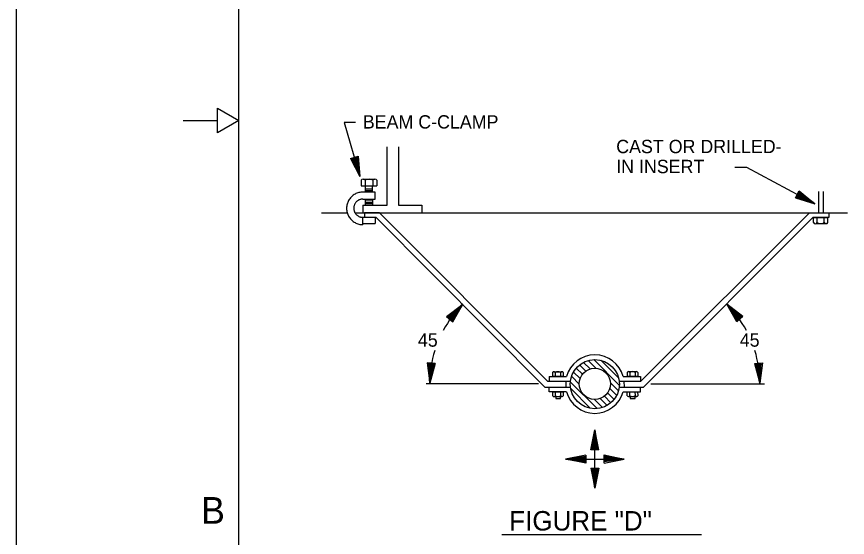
# Model space of a CAD drawing. Extents: x 10040.55 to 10045.84, y 10033.26 to 10035.76.
# Drawn here: x 10040.547 to 10041.17, y 10034.193 to 10034.583 of the extents above; entities that cross this region are included whole.
import ezdxf

# ---------------------------------------------------------------- set-up
doc = ezdxf.new("R2010")
doc.units = 0
doc.layers.add('Level 1', color=7, linetype='Continuous')
doc.layers.add('Level 2', color=7, linetype='Continuous')

msp = doc.modelspace()

# ---------------------------------------------------------------- linework, layer by layer
at = {"layer": 'Level 1'}
for p, q in [((10040.54697, 10033.25552), (10040.54697, 10035.75552)), ((10040.71364, 10033.29719), (10040.71364, 10035.71385)), ((10040.69764, 10034.49619), (10040.69764, 10034.5146)), ((10040.69764, 10034.5146), (10040.71364, 10034.50552)), ((10040.67197, 10034.50552), (10040.69764, 10034.50552)), ((10040.71364, 10034.50552), (10040.69764, 10034.49619))]:
    msp.add_line(p, q, dxfattribs=at)
at = {"layer": 'Level 2'}
for p, q in [((10040.82507, 10034.44193), (10040.82507, 10034.48575)), ((10040.83347, 10034.48575), (10040.83347, 10034.44193)), ((10040.79736, 10034.47697), (10040.80316, 10034.47861)), ((10040.80436, 10034.46331), (10040.80096, 10034.47799)), ((10040.80436, 10034.46331), (10040.80167, 10034.47821)), ((10040.80436, 10034.46331), (10040.80236, 10034.4784)), ((10040.80316, 10034.47861), (10040.80436, 10034.46331)), ((10040.79736, 10034.47697), (10040.80436, 10034.46331)), ((10040.80436, 10034.46331), (10040.79809, 10034.47719)), ((10040.80436, 10034.46331), (10040.79891, 10034.47744)), ((10040.80436, 10034.46331), (10040.79955, 10034.47759)), ((10040.80023, 10034.4778), (10040.80436, 10034.46331)), ((10040.8055, 10034.46057), (10040.80547, 10034.45646)), ((10040.80695, 10034.46146), (10040.81578, 10034.46146)), ((10040.8084, 10034.46056), (10040.8084, 10034.45646)), ((10040.81433, 10034.46057), (10040.81433, 10034.45643)), ((10040.81726, 10034.46057), (10040.81727, 10034.45646)), ((10040.80547, 10034.45646), (10040.81727, 10034.45646)), ((10040.81392, 10034.45399), (10040.80873, 10034.45399)), ((10040.80875, 10034.45172), (10040.80875, 10034.45642)), ((10040.81389, 10034.45172), (10040.81389, 10034.45642)), ((10040.81593, 10034.45172), (10040.80677, 10034.45172)), ((10040.80873, 10034.45294), (10040.81392, 10034.45294)), ((10040.81593, 10034.44646), (10040.81593, 10034.45172)), ((10041.13127, 10034.44748), (10041.13411, 10034.45279)), ((10041.13127, 10034.44748), (10041.14596, 10034.44303)), ((10041.14596, 10034.44303), (10041.13163, 10034.44816)), ((10041.14596, 10034.44303), (10041.13201, 10034.44892)), ((10041.14596, 10034.44303), (10041.13234, 10034.44949)), ((10041.13267, 10034.45011), (10041.14596, 10034.44303)), ((10041.14596, 10034.44303), (10041.13303, 10034.45078)), ((10041.14596, 10034.44303), (10041.13338, 10034.45144)), ((10041.14596, 10034.44303), (10041.13372, 10034.45207)), ((10041.13411, 10034.45279), (10041.14596, 10034.44303)), ((10041.1486, 10034.45223), (10041.1486, 10034.43634)), ((10041.15201, 10034.45223), (10041.15201, 10034.43634)), ((10040.80677, 10034.44646), (10040.81593, 10034.44646)), ((10040.80677, 10034.44193), (10040.82507, 10034.44193)), ((10040.80677, 10034.44193), (10040.80677, 10034.43622)), ((10040.81392, 10034.44557), (10040.80873, 10034.44557)), ((10040.81385, 10034.44303), (10040.80873, 10034.44303)), ((10040.80875, 10034.44189), (10040.80875, 10034.4465)), ((10040.80879, 10034.44416), (10040.81392, 10034.44416)), ((10040.81389, 10034.4465), (10040.81389, 10034.44189)), ((10040.83347, 10034.44193), (10040.8511, 10034.44193)), ((10040.8511, 10034.44193), (10040.8511, 10034.43622)), ((10040.77582, 10034.43628), (10040.79498, 10034.43628)), ((10040.80079, 10034.43628), (10041.17027, 10034.43628)), ((10040.8192, 10034.43628), (10040.80801, 10034.43622)), ((10040.80801, 10034.43622), (10040.80801, 10034.43288)), ((10040.8192, 10034.43628), (10040.94517, 10034.30983)), ((10041.01539, 10034.30989), (10041.14178, 10034.43628)), ((10041.14182, 10034.43628), (10041.15668, 10034.43628)), ((10041.15668, 10034.43285), (10041.15668, 10034.43628)), ((10040.80677, 10034.43288), (10040.81636, 10034.43288)), ((10040.80677, 10034.42726), (10040.80677, 10034.43278)), ((10040.80677, 10034.42828), (10040.81596, 10034.42828)), ((10040.81596, 10034.43278), (10040.81596, 10034.42828)), ((10040.81636, 10034.43288), (10040.94327, 10034.30549)), ((10041.01724, 10034.30549), (10041.1446, 10034.43285)), ((10041.1446, 10034.43285), (10041.15668, 10034.43285)), ((10041.14486, 10034.43256), (10041.15558, 10034.43256)), ((10041.14489, 10034.4288), (10041.14486, 10034.43256)), ((10041.14622, 10034.428), (10041.15425, 10034.42807)), ((10041.14752, 10034.42883), (10041.14752, 10034.43254)), ((10041.15293, 10034.42883), (10041.15293, 10034.43257)), ((10041.1556, 10034.42884), (10041.15558, 10034.43256)), ((10040.8696, 10034.35827), (10040.88179, 10034.36761)), ((10040.88179, 10034.36761), (10040.87018, 10034.35777)), ((10040.88179, 10034.36761), (10040.8708, 10034.3572)), ((10040.88179, 10034.36761), (10040.87131, 10034.35678)), ((10040.87183, 10034.35631), (10040.88179, 10034.36761)), ((10040.88179, 10034.36761), (10040.87242, 10034.35581)), ((10040.88179, 10034.36761), (10040.87296, 10034.35531)), ((10040.88179, 10034.36761), (10040.87351, 10034.35485)), ((10040.87415, 10034.35431), (10040.88179, 10034.36761)), ((10041.08969, 10034.35631), (10041.07973, 10034.36761)), ((10041.08738, 10034.35431), (10041.07973, 10034.36761)), ((10041.09192, 10034.35827), (10041.07973, 10034.36761)), ((10041.07973, 10034.36761), (10041.08856, 10034.35531)), ((10041.07973, 10034.36761), (10041.09072, 10034.3572)), ((10041.07973, 10034.36761), (10041.08801, 10034.35485)), ((10041.07973, 10034.36761), (10041.0891, 10034.35581)), ((10041.07973, 10034.36761), (10041.09021, 10034.35678)), ((10041.07973, 10034.36761), (10041.09134, 10034.35777)), ((10040.8696, 10034.35827), (10040.87415, 10034.35431)), ((10041.09192, 10034.35827), (10041.08738, 10034.35431)), ((10040.86106, 10034.32324), (10040.85504, 10034.32367)), ((10040.85504, 10034.32367), (10040.85701, 10034.30844)), ((10040.85701, 10034.30844), (10040.85586, 10034.3236)), ((10040.85701, 10034.30844), (10040.85658, 10034.32357)), ((10040.85701, 10034.30844), (10040.85733, 10034.32351)), ((10040.85808, 10034.32346), (10040.85701, 10034.30844)), ((10040.85701, 10034.30844), (10040.85879, 10034.32341)), ((10040.85701, 10034.30844), (10040.85946, 10034.32338)), ((10040.85701, 10034.30844), (10040.86029, 10034.3233)), ((10040.86106, 10034.32324), (10040.85701, 10034.30844)), ((10040.97724, 10034.31903), (10040.9723, 10034.32398)), ((10040.98163, 10034.31953), (10040.97577, 10034.3254)), ((10040.99933, 10034.30674), (10040.97995, 10034.32613)), ((10040.99883, 10034.31214), (10040.98532, 10034.32563)), ((10041.10046, 10034.32324), (10041.10648, 10034.32367)), ((10041.10046, 10034.32324), (10041.10451, 10034.30844)), ((10041.10451, 10034.30844), (10041.10123, 10034.3233)), ((10041.10451, 10034.30844), (10041.10206, 10034.32338)), ((10041.10451, 10034.30844), (10041.10273, 10034.32341)), ((10041.10344, 10034.32346), (10041.10451, 10034.30844)), ((10041.10451, 10034.30844), (10041.10419, 10034.32351)), ((10041.10648, 10034.32367), (10041.10451, 10034.30844)), ((10041.10451, 10034.30844), (10041.10566, 10034.3236)), ((10041.10451, 10034.30844), (10041.10494, 10034.32357)), ((10040.94908, 10034.31636), (10040.94907, 10034.31355)), ((10040.95008, 10034.31697), (10040.95611, 10034.31697)), ((10040.95106, 10034.31635), (10040.95106, 10034.31355)), ((10040.95511, 10034.31636), (10040.95511, 10034.31354)), ((10040.95711, 10034.31636), (10040.95713, 10034.31355)), ((10040.96974, 10034.31188), (10040.96489, 10034.31673)), ((10040.97149, 10034.31502), (10040.96689, 10034.31963)), ((10040.97398, 10034.31743), (10040.96935, 10034.32204)), ((10041.00504, 10034.31643), (10041.00503, 10034.31361)), ((10041.00604, 10034.31703), (10041.01207, 10034.31703)), ((10041.00702, 10034.31643), (10041.00702, 10034.31361)), ((10041.01107, 10034.31643), (10041.01107, 10034.31361)), ((10041.01307, 10034.31643), (10041.01308, 10034.31361)), ((10040.94517, 10034.30983), (10040.95908, 10034.30983)), ((10040.94642, 10034.31334), (10040.94642, 10034.30983)), ((10040.9465, 10034.31332), (10040.95958, 10034.31332)), ((10040.94907, 10034.31355), (10040.95713, 10034.31355)), ((10040.95908, 10034.30983), (10040.95911, 10034.30549)), ((10040.95908, 10034.30983), (10040.96249, 10034.30983)), ((10040.96905, 10034.30768), (10040.96342, 10034.31332)), ((10040.99908, 10034.30989), (10041.00267, 10034.30989)), ((10041.00197, 10034.31334), (10041.01514, 10034.31334)), ((10041.00267, 10034.30989), (10041.0027, 10034.30549)), ((10041.00267, 10034.30989), (10041.01539, 10034.30989)), ((10041.00503, 10034.31361), (10041.01308, 10034.31361)), ((10041.01514, 10034.31334), (10041.01514, 10034.30992)), ((10040.93854, 10034.30783), (10040.85435, 10034.30783)), ((10040.94327, 10034.30549), (10040.95911, 10034.30549)), ((10040.94643, 10034.30198), (10040.94643, 10034.30549)), ((10040.95911, 10034.30549), (10040.96249, 10034.30549)), ((10040.98246, 10034.2894), (10040.96261, 10034.30924)), ((10040.97725, 10034.2897), (10040.96292, 10034.30402)), ((10040.99719, 10034.29909), (10040.99194, 10034.30434)), ((10040.9986, 10034.30254), (10040.99245, 10034.30872)), ((10040.99909, 10034.30549), (10041.0027, 10034.30549)), ((10041.0027, 10034.30549), (10041.01724, 10034.30549)), ((10041.01514, 10034.30198), (10041.01514, 10034.30549)), ((10041.02272, 10034.30783), (10041.10816, 10034.30783)), ((10040.95959, 10034.30198), (10040.94643, 10034.30198)), ((10040.94916, 10034.30169), (10040.95721, 10034.30179)), ((10040.94921, 10034.29888), (10040.94916, 10034.30169)), ((10040.95022, 10034.29829), (10040.95625, 10034.29838)), ((10040.95119, 10034.29891), (10040.95116, 10034.3017)), ((10040.95524, 10034.29896), (10040.95521, 10034.30178)), ((10040.95726, 10034.29899), (10040.95721, 10034.30179)), ((10040.99283, 10034.29368), (10040.98793, 10034.29858)), ((10040.99525, 10034.29614), (10040.99032, 10034.30107)), ((10041.00197, 10034.30198), (10041.01514, 10034.30198)), ((10041.00511, 10034.30175), (10041.01317, 10034.30186)), ((10041.00517, 10034.29894), (10041.00511, 10034.30175)), ((10041.00618, 10034.29835), (10041.01222, 10034.29844)), ((10041.00716, 10034.29898), (10041.00711, 10034.30178)), ((10041.0112, 10034.29902), (10041.01117, 10034.30184)), ((10041.01321, 10034.29906), (10041.01317, 10034.30186)), ((10040.98654, 10034.2902), (10040.98059, 10034.29615)), ((10040.98995, 10034.29167), (10040.98477, 10034.29684)), ((10040.97784, 10034.25843), (10040.98086, 10034.27347)), ((10040.98086, 10034.27347), (10040.97866, 10034.25842)), ((10040.98086, 10034.27347), (10040.97939, 10034.25841)), ((10040.98086, 10034.27347), (10040.98013, 10034.25842)), ((10040.98086, 10034.22948), (10040.98086, 10034.27347)), ((10040.98089, 10034.25841), (10040.98086, 10034.27347)), ((10040.98386, 10034.25842), (10040.98086, 10034.27347)), ((10040.98086, 10034.27347), (10040.98226, 10034.2584)), ((10040.98086, 10034.27347), (10040.98158, 10034.25842)), ((10040.98086, 10034.27347), (10040.9831, 10034.25842)), ((10040.97393, 10034.25447), (10040.95888, 10034.25147)), ((10040.95888, 10034.25147), (10040.97393, 10034.25371)), ((10040.97393, 10034.25447), (10040.97392, 10034.24845)), ((10040.98386, 10034.25842), (10040.97784, 10034.25843)), ((10040.98781, 10034.24847), (10040.98782, 10034.25449)), ((10041.00286, 10034.25147), (10040.98781, 10034.25368)), ((10040.98782, 10034.25449), (10041.00286, 10034.25147)), ((10040.95888, 10034.25147), (10040.97395, 10034.25286)), ((10040.95888, 10034.25147), (10040.97393, 10034.25219)), ((10040.97394, 10034.25149), (10040.95888, 10034.25147)), ((10040.95888, 10034.25147), (10041.00286, 10034.25147)), ((10040.97392, 10034.24845), (10040.95888, 10034.25147)), ((10040.95888, 10034.25147), (10040.97394, 10034.24999)), ((10040.95888, 10034.25147), (10040.97393, 10034.24926)), ((10040.95888, 10034.25147), (10040.97393, 10034.25073)), ((10041.00286, 10034.25147), (10040.98779, 10034.25007)), ((10041.00286, 10034.25147), (10040.9878, 10034.25295)), ((10040.9878, 10034.25145), (10041.00286, 10034.25147)), ((10041.00286, 10034.25147), (10040.98781, 10034.25221)), ((10040.98781, 10034.24847), (10041.00286, 10034.25147)), ((10041.00286, 10034.25147), (10040.98781, 10034.25075)), ((10041.00286, 10034.25147), (10040.98781, 10034.24923)), ((10040.97786, 10034.24453), (10040.98389, 10034.24452)), ((10040.97786, 10034.24453), (10040.98086, 10034.22948)), ((10040.98086, 10034.22948), (10040.97863, 10034.24453)), ((10040.98086, 10034.22948), (10040.97947, 10034.24455)), ((10040.98086, 10034.22948), (10040.98015, 10034.24453)), ((10040.98084, 10034.24454), (10040.98086, 10034.22948)), ((10040.98086, 10034.22948), (10040.98234, 10034.24454)), ((10040.98086, 10034.22948), (10040.98307, 10034.24453)), ((10040.98086, 10034.22948), (10040.9816, 10034.24453)), ((10040.98389, 10034.24452), (10040.98086, 10034.22948)), ((10040.91101, 10034.19479), (10041.06094, 10034.19479))]:
    msp.add_line(p, q, dxfattribs=at)
for points in [[(10040.80118, 10034.50388), (10040.79283, 10034.50388), (10040.80436, 10034.46331)], [(10041.08592, 10034.47047), (10041.09466, 10034.47047), (10041.14596, 10034.44303)], [(10040.80677, 10034.45174), (10040.806, 10034.45172), (10040.80524, 10034.45165), (10040.80448, 10034.45152), (10040.80373, 10034.45135), (10040.80299, 10034.45115), (10040.80227, 10034.45089), (10040.80156, 10034.45057), (10040.80089, 10034.45023), (10040.80022, 10034.44984), (10040.79958, 10034.44941), (10040.79898, 10034.44894), (10040.79841, 10034.44843), (10040.79786, 10034.44789), (10040.79735, 10034.44731), (10040.79689, 10034.44671), (10040.79645, 10034.44607), (10040.79606, 10034.44541), (10040.79572, 10034.44473), (10040.79541, 10034.44402), (10040.79515, 10034.4433), (10040.79494, 10034.44256), (10040.79477, 10034.44181), (10040.79465, 10034.44105), (10040.79457, 10034.44029), (10040.79455, 10034.43952), (10040.79457, 10034.43876), (10040.79465, 10034.43799), (10040.79477, 10034.43724), (10040.79494, 10034.43649), (10040.79515, 10034.43575), (10040.79541, 10034.43503), (10040.79572, 10034.43432), (10040.79606, 10034.43364), (10040.79645, 10034.43298), (10040.79689, 10034.43234), (10040.79735, 10034.43174), (10040.79786, 10034.43117), (10040.79841, 10034.43061), (10040.79898, 10034.43011), (10040.79958, 10034.42965), (10040.80022, 10034.42921), (10040.80089, 10034.42882), (10040.80156, 10034.42847), (10040.80227, 10034.42817), (10040.80299, 10034.42791), (10040.80373, 10034.42769), (10040.80448, 10034.42752), (10040.80524, 10034.42741), (10040.806, 10034.42733), (10040.80677, 10034.42731)], [(10040.80677, 10034.44646), (10040.80633, 10034.44645), (10040.80591, 10034.44641), (10040.80549, 10034.44634), (10040.80506, 10034.44625), (10040.80466, 10034.44613), (10040.80425, 10034.44598), (10040.80385, 10034.44581), (10040.80347, 10034.44561), (10040.8031, 10034.4454), (10040.80275, 10034.44516), (10040.80241, 10034.4449), (10040.80208, 10034.4446), (10040.80178, 10034.4443), (10040.8015, 10034.44398), (10040.80123, 10034.44365), (10040.80099, 10034.44329), (10040.80077, 10034.44292), (10040.80057, 10034.44253), (10040.80041, 10034.44214), (10040.80026, 10034.44174), (10040.80015, 10034.44132), (10040.80005, 10034.44091), (10040.79998, 10034.44048), (10040.79994, 10034.44005), (10040.79993, 10034.43963), (10040.79994, 10034.4392), (10040.79998, 10034.43876), (10040.80005, 10034.43834), (10040.80015, 10034.43792), (10040.80026, 10034.43751), (10040.80041, 10034.4371), (10040.80057, 10034.43671), (10040.80077, 10034.43632), (10040.80099, 10034.43596), (10040.80123, 10034.4356), (10040.8015, 10034.43526), (10040.80178, 10034.43494), (10040.80208, 10034.43464), (10040.80241, 10034.43435), (10040.80275, 10034.43408), (10040.8031, 10034.43384), (10040.80347, 10034.43363), (10040.80385, 10034.43344), (10040.80425, 10034.43326), (10040.80466, 10034.43311), (10040.80506, 10034.433), (10040.80549, 10034.43291), (10040.80591, 10034.43283), (10040.80633, 10034.43279), (10040.80677, 10034.43278)], [(10040.95144, 10034.29833), (10040.95145, 10034.29676), (10040.955, 10034.29676), (10040.955, 10034.29833)], [(10041.00739, 10034.29841), (10041.0074, 10034.29682), (10041.01095, 10034.29682), (10041.01095, 10034.29841)]]:
    msp.add_lwpolyline(points, dxfattribs=at)
for centre, radius in [((10040.98081, 10034.30763), 0.01841), ((10040.98076, 10034.30786), 0.01172)]:
    msp.add_circle(centre, radius, dxfattribs=at)
for centre, radius, start, end in [((10040.80693, 10034.45979), 0.00165, 27.91313, 152.05962), ((10040.81136, 10034.456), 0.00545, 57.03159, 122.96841), ((10040.81579, 10034.45977), 0.00167, 28.34206, 151.66132), ((10041.1462, 10034.42952), 0.0015, 208.16061, 332.3071), ((10041.15021, 10034.43299), 0.00495, 237.25183, 303.18864), ((10041.15425, 10034.42957), 0.00152, 208.55891, 331.87817), ((10040.94006, 10034.30844), 0.08305, 134.56125, 151.61924), ((10041.02146, 10034.30844), 0.08305, 28.38076, 45.43875), ((10040.94006, 10034.30844), 0.08305, 162.97004, 180), ((10040.98078, 10034.30766), 0.02194, 15.01092, 164.9726), ((10041.02146, 10034.30844), 0.08305, 0, 17.02996), ((10040.95007, 10034.31583), 0.00113, 27.91313, 152.05962), ((10040.95309, 10034.31324), 0.00372, 57.03159, 122.96841), ((10040.95612, 10034.31582), 0.00114, 28.34206, 151.66132), ((10041.00603, 10034.3159), 0.00113, 27.91313, 152.05962), ((10041.00905, 10034.31331), 0.00372, 57.03159, 122.96841), ((10041.01208, 10034.31589), 0.00114, 28.34206, 151.66132), ((10040.95019, 10034.29942), 0.00113, 208.78561, 332.9321), ((10040.95317, 10034.30205), 0.00372, 237.87682, 303.81364), ((10040.95624, 10034.29952), 0.00114, 209.18391, 332.50317), ((10040.98078, 10034.30766), 0.02194, 194.97776, 344.98899), ((10041.00615, 10034.29948), 0.00113, 208.78561, 332.9321), ((10041.00913, 10034.30212), 0.00372, 237.87682, 303.81364), ((10041.0122, 10034.29959), 0.00114, 209.18391, 332.50317)]:
    msp.add_arc(centre, radius, start, end, dxfattribs=at)

# ---------------------------------------------------------------- texts
at = {"layer": 'Level 1'}
msp.add_text('B', height=0.02, dxfattribs=at).set_placement((10040.68539, 10034.2029))
at = {"layer": 'Level 2'}
for s, height, p in [('BEAM C-CLAMP', 0.01, (10040.8067, 10034.49941)), ('CAST OR DRILLED-', 0.01, (10040.99683, 10034.48093)), ('IN INSERT', 0.01, (10040.99683, 10034.46593)), ('45', 0.01, (10040.84801, 10034.33572)), ('45', 0.01, (10041.08953, 10034.33572)), ('FIGURE "D"', 0.014583, (10040.91658, 10034.19782))]:
    msp.add_text(s, height=height, dxfattribs=at).set_placement(p)

doc.saveas('drawing.dxf')
